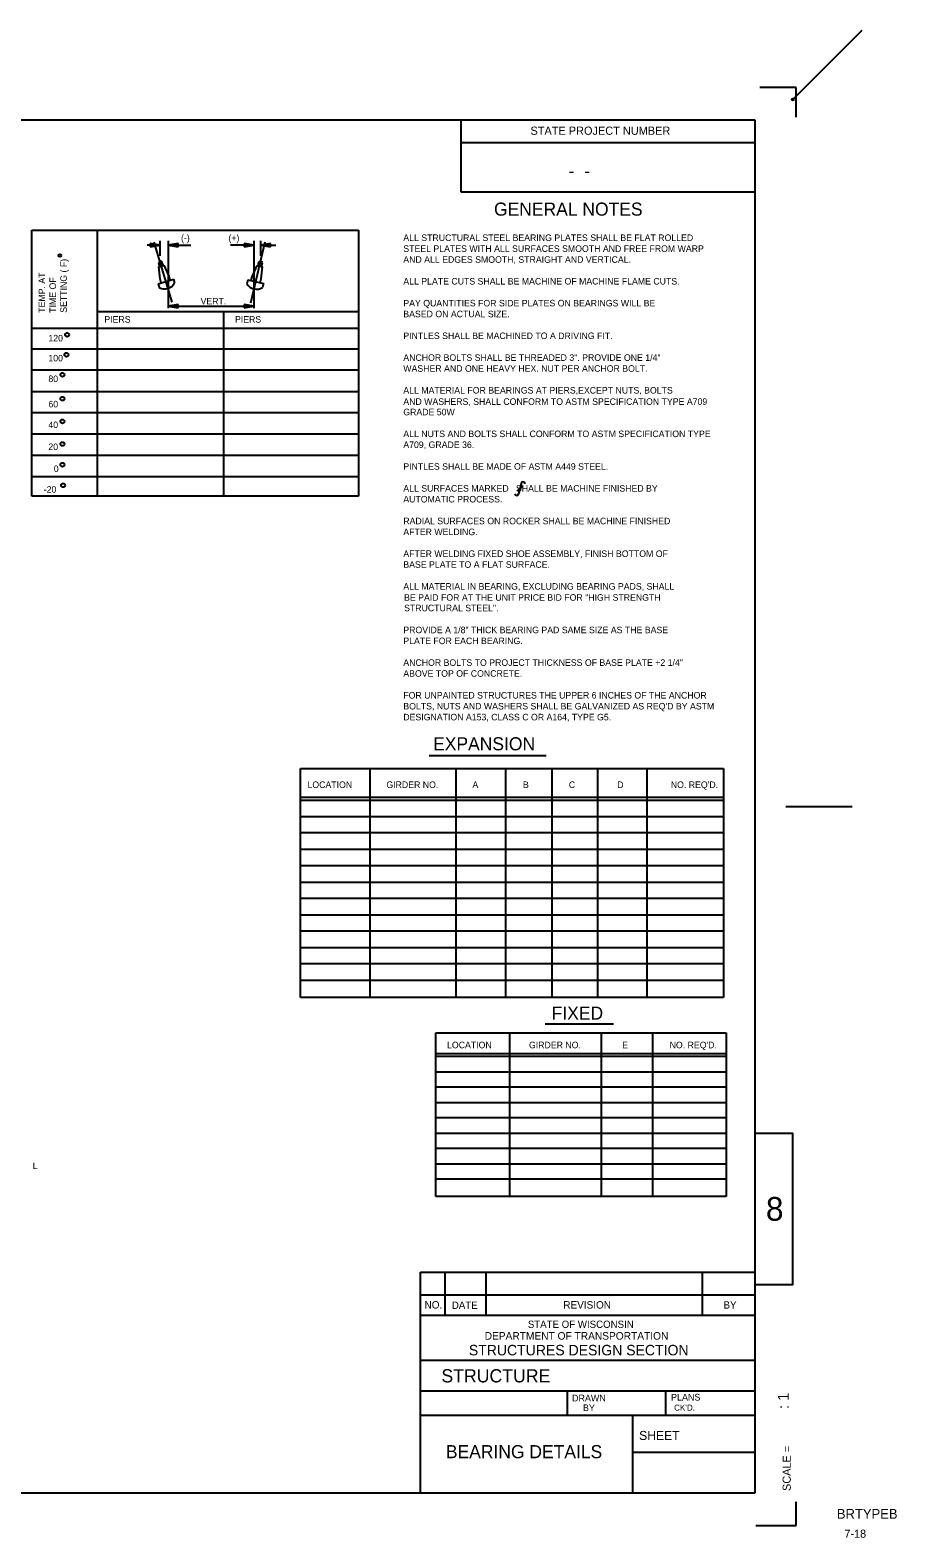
# Model space of a CAD drawing. Extents: x -1.11 to 1.95, y -0.95 to 1.09.
# Drawn here: x 0.847 to 1.952, y -0.876 to 1.046 of the extents above; entities that cross this region are included whole.
import ezdxf

# ---------------------------------------------------------------- set-up
doc = ezdxf.new("R2010")
doc.units = 0
for name, color, linetype in [('Level 1', 7, 'Continuous'), ('Level 2', 7, 'Continuous'), ('Level 3', 7, 'Continuous'), ('Level 37', 7, 'Continuous'), ('Level 49', 7, 'Continuous')]:
    doc.layers.add(name, color=color, linetype=linetype)

msp = doc.modelspace()

# ---------------------------------------------------------------- linework, layer by layer
at = {"layer": 'Level 1'}
for p, q in [((1.8236, 0.9726), (1.7774, 0.9726)), ((1.8236, 0.9346), (1.8236, 0.9726)), ((1.7715, 0.9309), (-0.8431, 0.9309)), ((1.396, 0.9309), (1.396, 0.8396)), ((1.7715, -0.8191), (1.7715, 0.9309)), ((1.396, 0.9022), (1.7715, 0.9022)), ((1.396, 0.8396), (1.7715, 0.8396)), ((0.8489, 0.4517), (0.8489, 0.7908)), ((0.8489, 0.7908), (1.2654, 0.7908)), ((0.932, 0.7908), (0.932, 0.6658)), ((1.2654, 0.7908), (1.2654, 0.4517)), ((1.0123, 0.7715), (0.996, 0.7715)), ((0.9998, 0.7736), (0.9998, 0.7694)), ((1.0123, 0.7715), (0.9998, 0.7736)), ((0.9998, 0.7694), (1.0123, 0.7715)), ((1.0123, 0.7578), (1.0123, 0.7772)), ((1.0228, 0.7772), (1.0228, 0.6911)), ((1.0353, 0.7736), (1.0228, 0.7715)), ((1.0228, 0.7715), (1.0515, 0.7715)), ((1.0228, 0.7715), (1.0353, 0.7694)), ((1.0353, 0.7694), (1.0353, 0.7736)), ((1.132, 0.7715), (1.1021, 0.7715)), ((1.1195, 0.7736), (1.1195, 0.7694)), ((1.132, 0.7715), (1.1195, 0.7736)), ((1.1195, 0.7694), (1.132, 0.7715)), ((1.132, 0.7772), (1.132, 0.6911)), ((1.1408, 0.7578), (1.1408, 0.7772)), ((1.1533, 0.7736), (1.1408, 0.7715)), ((1.1408, 0.7715), (1.1601, 0.7715)), ((1.1408, 0.7715), (1.1533, 0.7694)), ((1.1533, 0.7694), (1.1533, 0.7736)), ((1.0163, 0.7456), (1.0148, 0.7503)), ((1.1373, 0.7453), (1.1384, 0.7502)), ((1.012, 0.7443), (1.0106, 0.7491)), ((1.0108, 0.7439), (1.0176, 0.746)), ((1.0124, 0.7284), (1.0108, 0.7439)), ((1.0238, 0.7318), (1.0176, 0.746)), ((1.0253, 0.7269), (1.0238, 0.7318)), ((1.1285, 0.7263), (1.1297, 0.7313)), ((1.1297, 0.7313), (1.136, 0.7456)), ((1.136, 0.7456), (1.1428, 0.744)), ((1.1413, 0.7286), (1.1428, 0.744)), ((1.1416, 0.7443), (1.1428, 0.7491)), ((1.0098, 0.7223), (1.0293, 0.7282)), ((1.0098, 0.7223), (1.0113, 0.7174)), ((1.0139, 0.7235), (1.0124, 0.7284)), ((1.0293, 0.7282), (1.0308, 0.7233)), ((1.1243, 0.7273), (1.1232, 0.7223)), ((1.1243, 0.7273), (1.1443, 0.7227)), ((1.1401, 0.7236), (1.1413, 0.7286)), ((1.1443, 0.7227), (1.1431, 0.7177)), ((1.0353, 0.6957), (1.0228, 0.6936)), ((1.0228, 0.6936), (1.132, 0.6936)), ((1.0228, 0.6936), (1.0353, 0.6915)), ((1.0353, 0.6915), (1.0353, 0.6957)), ((1.1195, 0.6957), (1.1195, 0.6915)), ((1.132, 0.6936), (1.1195, 0.6957)), ((1.1195, 0.6915), (1.132, 0.6936)), ((0.932, 0.6871), (1.2651, 0.6871)), ((1.0934, 0.6871), (1.0934, 0.4517)), ((0.8487, 0.6658), (1.2651, 0.6658)), ((0.932, 0.6658), (0.932, 0.4517)), ((0.8487, 0.6395), (1.2651, 0.6395)), ((1.2651, 0.6123), (0.8487, 0.6123)), ((0.8487, 0.5851), (1.2651, 0.5851)), ((1.2651, 0.5579), (0.8487, 0.5579)), ((0.8487, 0.5308), (1.2651, 0.5308)), ((1.2651, 0.5035), (0.8487, 0.5035)), ((1.2651, 0.4763), (0.8487, 0.4763)), ((1.4745, 0.4638), (1.4679, 0.4581)), ((1.4728, 0.4673), (1.4697, 0.4546)), ((1.2654, 0.4517), (0.8489, 0.4517)), ((1.3555, 0.1207), (1.5046, 0.1207)), ((1.1913, 0.1043), (1.7311, 0.1043)), ((1.1913, -0.1878), (1.1913, 0.1043)), ((1.28, 0.1043), (1.28, -0.1878)), ((1.3895, 0.1043), (1.3895, -0.1878)), ((1.4533, -0.1878), (1.4533, 0.1043)), ((1.512, 0.1043), (1.512, -0.1878)), ((1.5707, -0.1878), (1.5707, 0.1043)), ((1.6333, 0.1043), (1.6333, -0.1878)), ((1.7311, 0.1043), (1.7311, -0.1878)), ((1.1913, 0.0678), (1.7311, 0.0678)), ((1.1913, 0.0639), (1.7311, 0.0639)), ((1.1913, 0.043), (1.7311, 0.043)), ((1.7311, 0.0222), (1.1913, 0.0222)), ((1.1913, 0.0013), (1.7311, 0.0013)), ((1.7311, -0.0196), (1.1913, -0.0196)), ((1.1913, -0.0404), (1.7311, -0.0404)), ((1.7311, -0.0613), (1.1913, -0.0613)), ((1.1913, -0.0821), (1.7311, -0.0821)), ((1.7311, -0.103), (1.1913, -0.103)), ((1.1913, -0.1238), (1.7311, -0.1238)), ((1.7311, -0.1447), (1.1913, -0.1447)), ((1.1913, -0.1656), (1.7311, -0.1656)), ((1.7311, -0.1878), (1.1913, -0.1878)), ((1.5036, -0.221), (1.5909, -0.221)), ((1.3641, -0.2328), (1.7343, -0.2328)), ((1.3641, -0.4413), (1.3641, -0.2328)), ((1.4579, -0.2328), (1.4579, -0.4413)), ((1.5753, -0.4413), (1.5753, -0.2328)), ((1.6404, -0.2328), (1.6404, -0.4413)), ((1.7343, -0.2328), (1.7343, -0.4413)), ((1.3641, -0.2588), (1.7343, -0.2588)), ((1.7343, -0.2628), (1.3641, -0.2628)), ((1.3641, -0.2823), (1.7343, -0.2823)), ((1.7343, -0.3018), (1.3641, -0.3018)), ((1.3641, -0.3214), (1.7343, -0.3214)), ((1.7343, -0.3409), (1.3641, -0.3409)), ((1.3641, -0.3605), (1.7343, -0.3605)), ((1.7343, -0.3801), (1.3641, -0.3801)), ((1.3641, -0.3996), (1.7343, -0.3996)), ((1.7343, -0.4192), (1.3641, -0.4192)), ((1.7343, -0.4413), (1.3641, -0.4413)), ((1.3445, -0.5379), (1.7718, -0.5379)), ((1.3445, -0.5925), (1.3445, -0.5379)), ((1.3761, -0.5925), (1.3761, -0.5379)), ((1.4281, -0.5925), (1.4281, -0.5379)), ((1.7041, -0.5925), (1.7041, -0.5379)), ((1.3445, -0.5665), (1.7718, -0.5665)), ((1.3445, -0.8191), (1.3445, -0.5925)), ((1.3445, -0.5925), (1.7718, -0.5925)), ((1.3445, -0.6498), (1.7718, -0.6498)), ((1.3445, -0.6889), (1.7718, -0.6889)), ((1.5321, -0.7201), (1.5321, -0.6889)), ((1.6576, -0.7201), (1.6576, -0.6889)), ((1.3445, -0.7201), (1.7718, -0.7201)), ((1.6153, -0.8191), (1.6153, -0.7201)), ((1.6154, -0.767), (1.7715, -0.767)), ((-0.8431, -0.8191), (1.7715, -0.8191)), ((1.8236, -0.8608), (1.8236, -0.8305)), ((1.7722, -0.8608), (1.8236, -0.8608))]:
    msp.add_line(p, q, dxfattribs=at)
msp.add_lwpolyline([(1.7715, -0.3604), (1.8188, -0.3604), (1.8188, -0.5538), (1.7715, -0.5538)], close=True, dxfattribs=at)
for centre, radius in [((0.8844, 0.7584), 0.00167), ((0.8938, 0.6573), 0.0025), ((0.8929, 0.6318), 0.0025), ((0.8878, 0.6063), 0.0025), ((0.8878, 0.5758), 0.0025), ((0.8878, 0.5468), 0.0025), ((0.8878, 0.518), 0.0025), ((0.8878, 0.4916), 0.0025), ((0.8887, 0.4653), 0.0025)]:
    msp.add_circle(centre, radius, dxfattribs=at)
for centre, radius, start, end in [((1.0131, 0.7486), 0.00247, 45, 168.6901), ((1.1403, 0.7485), 0.00257, 13.134, 137.7263), ((1.0182, 0.73), 0.0143, 241.496, 331.9471), ((1.1354, 0.7298), 0.0144, 211.4768, 302.2165), ((1.4752, 0.4673), 0.00242, 1.9749, 178.0251), ((1.4673, 0.4548), 0.00243, 185.9061, 354.0939)]:
    msp.add_arc(centre, radius, start, end, dxfattribs=at)
at = {"layer": 'Level 2'}
msp.add_line((1.8194, 0.9572), (1.9077, 1.0456), dxfattribs=at)
at = {"layer": 'Level 3'}
for p, q in [((1.0279, 0.6988), (1.0048, 0.7755)), ((1.1283, 0.6979), (1.1466, 0.7759))]:
    msp.add_line(p, q, dxfattribs=at)
at = {"layer": 'Level 37'}
msp.add_line((1.8107, 0.0559), (1.8949, 0.0559), dxfattribs=at)
at = {"layer": 'Level 49'}
msp.add_circle((1.8193, 0.9572), 0.00127, dxfattribs=at)

# ---------------------------------------------------------------- texts
at = {"layer": 'Level 1'}
for s, height, p in [('STATE PROJECT NUMBER', 0.010437, (1.4848, 0.9122)), ('    -  -  ', 0.01685, (1.5082, 0.8578)), ('GENERAL NOTES', 0.016667, (1.4383, 0.8091)), ('(-)', 0.00833, (1.0391, 0.7765)), ('(+)', 0.00833, (1.0996, 0.7765)), ('ALL STRUCTURAL STEEL BEARING PLATES SHALL BE FLAT ROLLED', 0.008334, (1.3226, 0.7768)), ('STEEL PLATES WITH ALL SURFACES SMOOTH AND FREE FROM WARP', 0.008334, (1.3226, 0.7629)), ('AND ALL EDGES SMOOTH, STRAIGHT AND VERTICAL.', 0.008334, (1.3226, 0.749)), ('ALL PLATE CUTS SHALL BE MACHINE OF MACHINE FLAME CUTS.', 0.008334, (1.3226, 0.7213)), ('VERT.', 0.00833, (1.064, 0.696)), ('PAY QUANTITIES FOR SIDE PLATES ON BEARINGS WILL BE', 0.008334, (1.3226, 0.6934)), ('PIERS', 0.00833, (0.9413, 0.6727)), ('PIERS', 0.00833, (1.1079, 0.6727)), ('BASED ON ACTUAL SIZE.', 0.008334, (1.3226, 0.6796)), ('120', 0.00833, (0.8699, 0.6488)), ('PINTLES SHALL BE MACHINED TO A DRIVING FIT.', 0.008334, (1.3226, 0.6518)), ('100', 0.00833, (0.8699, 0.6233)), ('ANCHOR BOLTS SHALL BE THREADED 3". PROVIDE ONE 1/4"', 0.008334, (1.3226, 0.624)), ('WASHER AND ONE HEAVY HEX. NUT PER ANCHOR BOLT.', 0.008334, (1.3226, 0.6101)), ('80', 0.00833, (0.8699, 0.597)), ('ALL MATERIAL FOR BEARINGS AT PIERS,EXCEPT NUTS, BOLTS ', 0.008334, (1.3226, 0.5823)), ('60', 0.00833, (0.8699, 0.5647)), ('AND WASHERS, SHALL CONFORM TO ASTM SPECIFICATION TYPE A709', 0.008334, (1.3226, 0.5679)), ('GRADE 50W', 0.00833, (1.3226, 0.5546)), ('40', 0.00833, (0.8699, 0.5383)), ('ALL NUTS AND BOLTS SHALL CONFORM TO ASTM SPECIFICATION TYPE ', 0.008334, (1.3226, 0.5268)), ('A709, GRADE 36.', 0.008334, (1.3226, 0.5129)), ('20', 0.00833, (0.8699, 0.5103)), ('0', 0.00833, (0.8768, 0.4823)), ('PINTLES SHALL BE MADE OF ASTM A449 STEEL.', 0.008334, (1.3226, 0.4852)), ('-20', 0.00833, (0.864, 0.4559)), ('ALL SURFACES MARKED   SHALL BE MACHINE FINISHED BY', 0.008334, (1.3226, 0.4573)), ('AUTOMATIC PROCESS.', 0.008334, (1.3226, 0.4435)), ('RADIAL SURFACES ON ROCKER SHALL BE MACHINE FINISHED', 0.008334, (1.3226, 0.4157)), ('AFTER WELDING.', 0.008334, (1.3226, 0.4018)), ('AFTER WELDING FIXED SHOE ASSEMBLY, FINISH BOTTOM OF', 0.008334, (1.3226, 0.374)), ('BASE PLATE TO A FLAT SURFACE.', 0.008334, (1.3226, 0.3602)), ('ALL MATERIAL IN BEARING, EXCLUDING BEARING PADS, SHALL', 0.008334, (1.3226, 0.3323)), ('STRUCTURAL STEEL".', 0.008334, (1.3236, 0.3048)), ('BE PAID FOR AT THE UNIT PRICE BID FOR "HIGH STRENGTH', 0.008334, (1.3236, 0.3182)), ('PROVIDE A 1/8" THICK BEARING PAD SAME SIZE AS THE BASE', 0.008334, (1.3226, 0.2768)), ('PLATE FOR EACH BEARING.', 0.008334, (1.3226, 0.2629)), ('ANCHOR BOLTS TO PROJECT THICKNESS OF BASE PLATE +2 1/4"', 0.008334, (1.3226, 0.2352)), ('ABOVE TOP OF CONCRETE.', 0.008334, (1.3226, 0.2213)), ('FOR UNPAINTED STRUCTURES THE UPPER 6 INCHES OF THE ANCHOR', 0.008334, (1.3226, 0.1935)), ("BOLTS, NUTS AND WASHERS SHALL BE GALVANIZED AS REQ'D BY ASTM", 0.008334, (1.3226, 0.1796)), ('DESIGNATION A153, CLASS C OR A164, TYPE G5.', 0.008334, (1.3226, 0.1657)), ('EXPANSION', 0.01667, (1.3606, 0.1275)), ('LOCATION   ', 0.008334, (1.2004, 0.0795)), ('GIRDER NO.', 0.00833, (1.301, 0.0795)), ('A ', 0.00833, (1.4108, 0.0795)), ('B', 0.00833, (1.4752, 0.0795)), ('C', 0.00833, (1.5337, 0.0795)), ('D', 0.00833, (1.5955, 0.0795)), ("NO. REQ'D.", 0.00833, (1.6638, 0.0795)), ('FIXED', 0.01667, (1.5118, -0.2158)), ('LOCATION', 0.00833, (1.3784, -0.2523)), ('GIRDER NO.', 0.00833, (1.4829, -0.2523)), ('E', 0.00833, (1.6018, -0.2523)), ("NO. REQ'D.", 0.00833, (1.6623, -0.2523)), ('L', 0.00833, (0.8499, -0.4063)), ('8', 0.0301, (1.7851, -0.4721)), ('NO.', 0.00949, (1.3497, -0.5841)), ('DATE', 0.00924, (1.3845, -0.5845)), ('REVISION', 0.00951, (1.5267, -0.5842)), ('BY', 0.00924, (1.7311, -0.5842)), ('DEPARTMENT OF TRANSPORTATION', 0.009702, (1.4264, -0.6238)), ('STATE OF WISCONSIN', 0.00923, (1.4814, -0.6088)), ('STRUCTURES DESIGN SECTION', 0.013375, (1.4062, -0.6438)), ('STRUCTURE', 0.01685, (1.3712, -0.6783)), ('DRAWN', 0.00852, (1.5378, -0.7025)), ('BY', 0.0085, (1.5518, -0.7149)), ('PLANS', 0.00853, (1.6641, -0.7014)), ("CK'D.", 0.00772, (1.668, -0.7143)), ('SHEET', 0.01156, (1.6234, -0.7517)), ('BEARING DETAILS', 0.016667, (1.3769, -0.7749)), ('BRTYPEB', 0.0124, (1.8756, -0.852)), ('7-18', 0.01033, (1.8852, -0.8763))]:
    msp.add_text(s, height=height, dxfattribs=at).set_placement(p)
for s, height, p in [('SETTING ( F)', 0.008334, (0.8935, 0.6853)), ('TEMP. AT', 0.00833, (0.8657, 0.6853)), ('TIME OF', 0.00833, (0.8796, 0.6853)), ('SCALE =          ', 0.010417, (1.8168, -0.8167))]:
    msp.add_text(s, height=height, rotation=90, dxfattribs=at).set_placement(p)
at = {"layer": 'Level 2'}
msp.add_text(': 1', height=0.014, rotation=90, dxfattribs=at).set_placement((1.8143, -0.7122))

doc.saveas('drawing.dxf')
